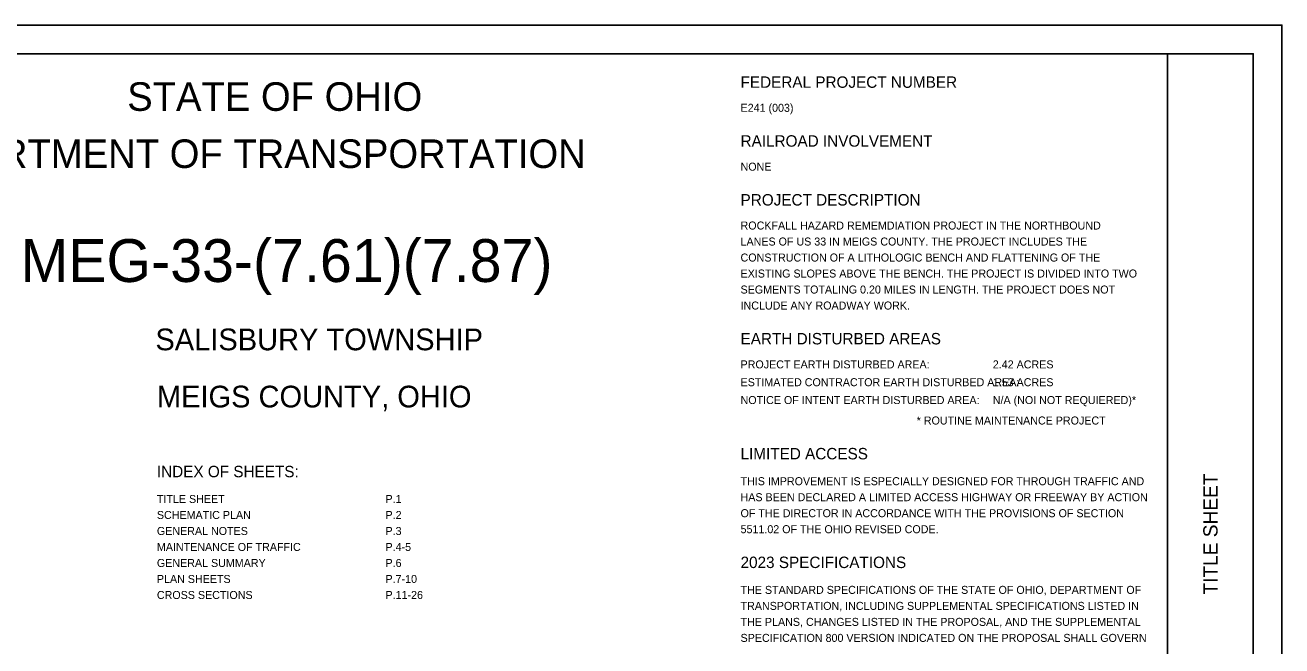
# Model space of a CAD drawing. Extents: x -20.2 to 34, y 0 to 22.
# Drawn here: x 12.01 to 34, y 11.14 to 22 of the extents above; entities that cross this region are included whole.
import ezdxf

# ---------------------------------------------------------------- set-up
doc = ezdxf.new("R2010")
doc.units = 0
for name, color, linetype in [('SH_Border', 7, 'Continuous'), ('SH_Cut_Line', 7, 'Continuous'), ('SH_Data', 7, 'Continuous'), ('SH_Text', 7, 'Continuous')]:
    doc.layers.add(name, color=color, linetype=linetype)

msp = doc.modelspace()

# ---------------------------------------------------------------- linework, layer by layer
at = {"layer": 'SH_Border'}
msp.add_line((32, 0.5), (32, 21.5), dxfattribs=at)
msp.add_lwpolyline([(1.5, 21.5), (33.5, 21.5), (33.5, 0.5), (1.5, 0.5)], close=True, dxfattribs=at)
at = {"layer": 'SH_Cut_Line'}
msp.add_lwpolyline([(0, 0), (34, 0), (34, 22), (0, 22)], close=True, dxfattribs=at)

# ---------------------------------------------------------------- texts
at = {"layer": 'SH_Data'}
msp.add_text('TITLE SHEET', height=0.25, rotation=90, dxfattribs=at).set_placement((32.875, 12.035))
at = {"layer": 'SH_Text'}
for s, height, p in [('STATE OF OHIO', 0.5, (13.795, 20.5)), ('FEDERAL PROJECT NUMBER', 0.2, (24.528, 20.903)), ('E241 (003)', 0.14, (24.528, 20.483)), ('RAILROAD INVOLVEMENT', 0.2, (24.528, 19.873)), ('DEPARTMENT OF TRANSPORTATION', 0.5, (9.747, 19.5)), ('NONE', 0.14, (24.528, 19.453)), ('PROJECT DESCRIPTION', 0.2, (24.528, 18.843)), ('ROCKFALL HAZARD REMEMDIATION PROJECT IN THE NORTHBOUND ', 0.14, (24.528, 18.423)), ('MEG-33-(7.61)(7.87)', 0.75, (11.929, 17.505)), ('LANES OF US 33 IN MEIGS COUNTY. THE PROJECT INCLUDES THE ', 0.14, (24.528, 18.143)), ('CONSTRUCTION OF A LITHOLOGIC BENCH AND FLATTENING OF THE ', 0.14, (24.528, 17.863)), ('EXISTING SLOPES ABOVE THE BENCH. THE PROJECT IS DIVIDED INTO TWO ', 0.14, (24.528, 17.583)), ('SEGMENTS TOTALING 0.20 MILES IN LENGTH. THE PROJECT DOES NOT ', 0.14, (24.528, 17.303)), ('INCLUDE ANY ROADWAY WORK.', 0.14, (24.528, 17.023)), ('SALISBURY TOWNSHIP', 0.38, (14.289, 16.31)), ('EARTH DISTURBED AREAS', 0.2, (24.528, 16.413)), ('PROJECT EARTH DISTURBED AREA:', 0.14, (24.528, 15.993)), ('2.42 ACRES', 0.14, (28.942, 15.993)), ('MEIGS COUNTY, OHIO', 0.38, (14.315, 15.31)), ('ESTIMATED CONTRACTOR EARTH DISTURBED AREA:', 0.14, (24.528, 15.681)), ('1.53 ACRES', 0.14, (28.942, 15.681)), ('NOTICE OF INTENT EARTH DISTURBED AREA:', 0.14, (24.528, 15.369)), ('N/A (NOI NOT REQUIERED)*', 0.14, (28.942, 15.369)), ('* ROUTINE MAINTENANCE PROJECT', 0.14, (27.61, 15.011)), ('LIMITED ACCESS', 0.2, (24.528, 14.401)), ('INDEX OF SHEETS:', 0.2, (14.315, 14.088)), ('THIS IMPROVEMENT IS ESPECIALLY DESIGNED FOR THROUGH TRAFFIC AND', 0.14, (24.528, 13.949)), ('TITLE SHEET', 0.14, (14.315, 13.638)), ('P.1', 0.14, (18.315, 13.638)), ('HAS BEEN DECLARED A LIMITED ACCESS HIGHWAY OR FREEWAY BY ACTION', 0.14, (24.528, 13.669)), ('SCHEMATIC PLAN', 0.14, (14.315, 13.358)), ('P.2', 0.14, (18.315, 13.358)), ('OF THE DIRECTOR IN ACCORDANCE WITH THE PROVISIONS OF SECTION', 0.14, (24.528, 13.389)), ('GENERAL NOTES', 0.14, (14.315, 13.078)), ('P.3', 0.14, (18.315, 13.078)), ('5511.02 OF THE OHIO REVISED CODE.', 0.14, (24.528, 13.109)), ('MAINTENANCE OF TRAFFIC', 0.14, (14.315, 12.798)), ('P.4-5', 0.14, (18.315, 12.798)), ('GENERAL SUMMARY', 0.14, (14.315, 12.518)), ('P.6', 0.14, (18.315, 12.518)), ('2023 SPECIFICATIONS', 0.2, (24.528, 12.499)), ('PLAN SHEETS', 0.14, (14.315, 12.238)), ('P.7-10', 0.14, (18.315, 12.238)), ('CROSS SECTIONS', 0.14, (14.315, 11.958)), ('P.11-26', 0.14, (18.315, 11.958)), ('THE STANDARD SPECIFICATIONS OF THE STATE OF OHIO, DEPARTMENT OF', 0.14, (24.528, 12.047)), ('TRANSPORTATION, INCLUDING SUPPLEMENTAL SPECIFICATIONS LISTED IN', 0.14, (24.528, 11.767)), ('THE PLANS, CHANGES LISTED IN THE PROPOSAL, AND THE SUPPLEMENTAL', 0.14, (24.528, 11.487)), ('SPECIFICATION 800 VERSION INDICATED ON THE PROPOSAL SHALL GOVERN', 0.14, (24.528, 11.207))]:
    msp.add_text(s, height=height, dxfattribs=at).set_placement(p)

doc.saveas('drawing.dxf')
